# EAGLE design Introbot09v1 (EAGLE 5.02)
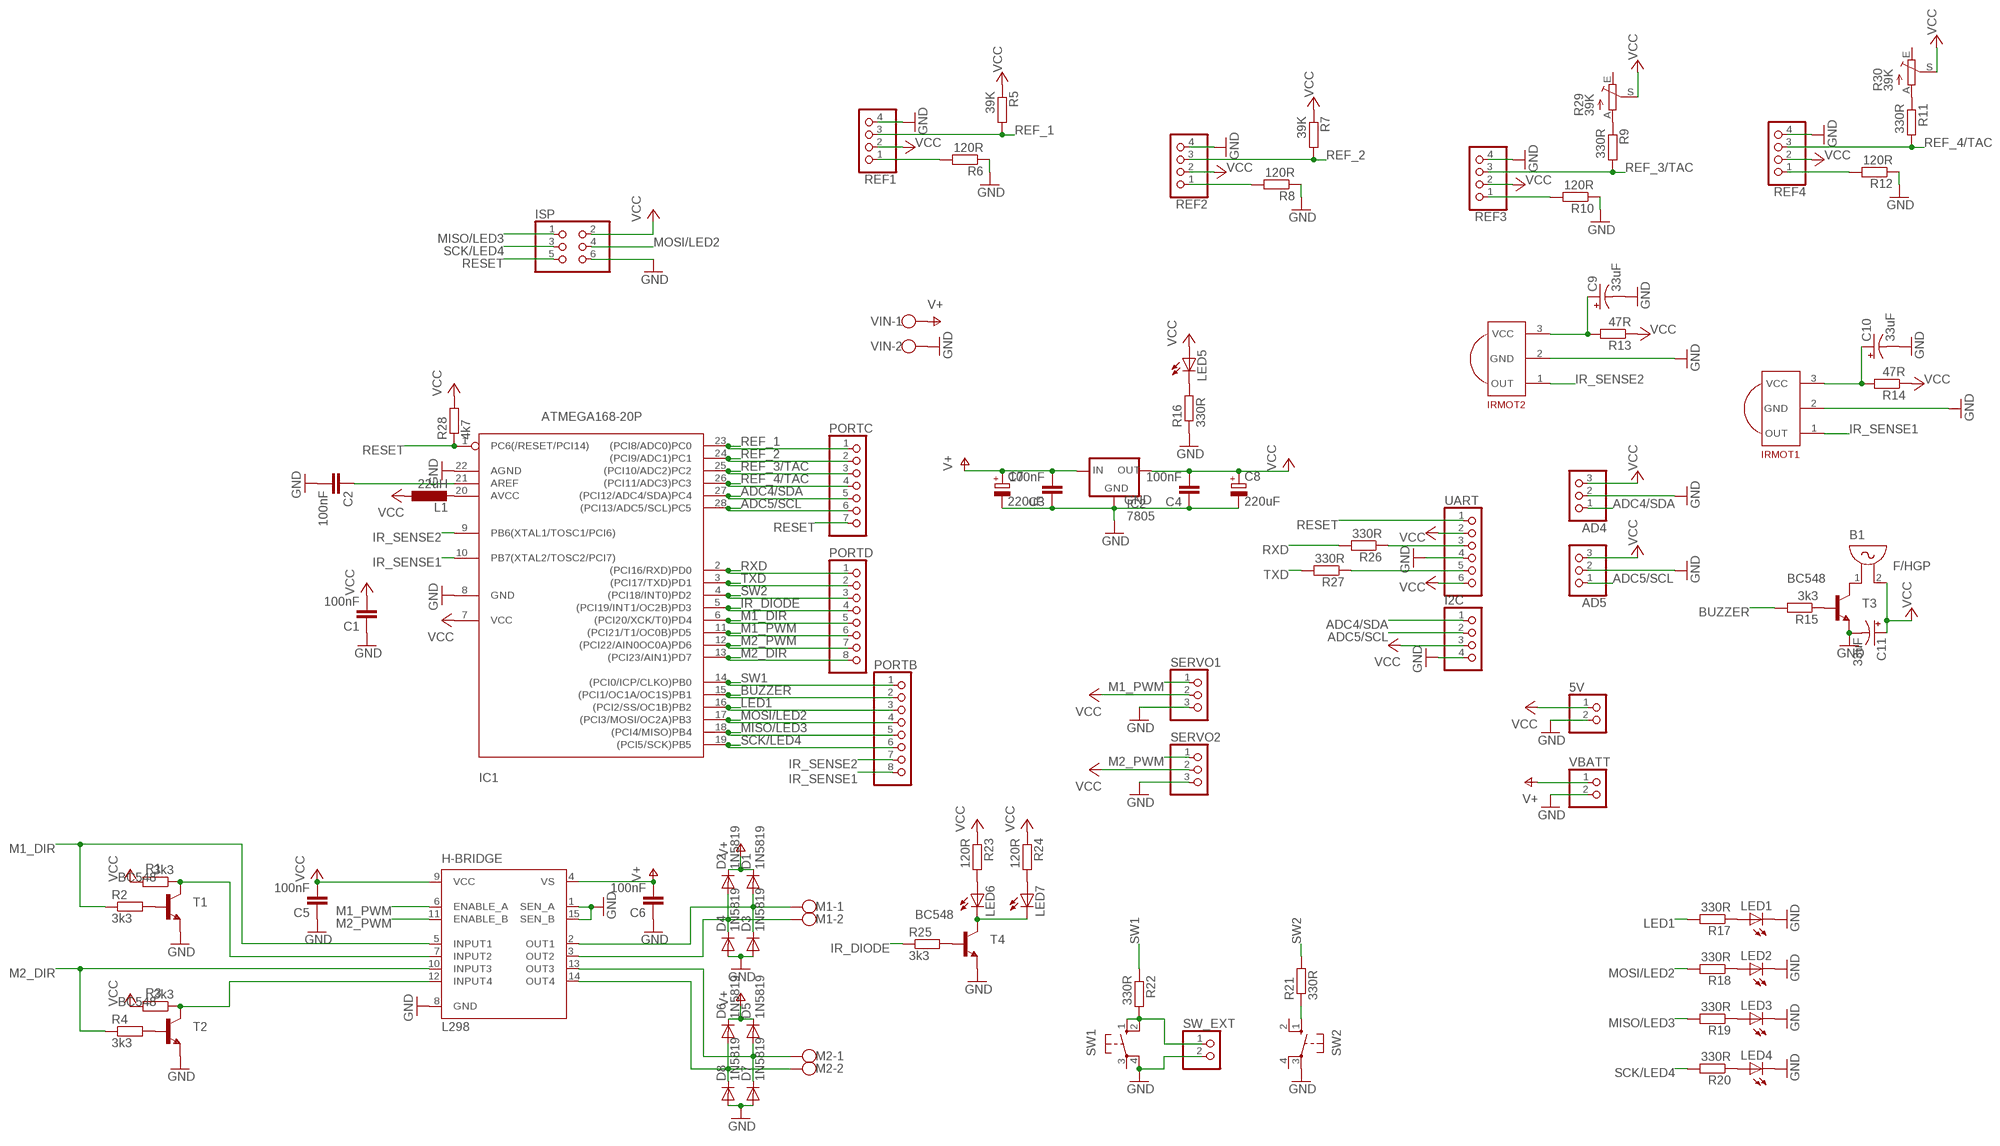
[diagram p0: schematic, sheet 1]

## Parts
5V  PINHD-1X2  [1X02]
AD4  PINHD-1X3H  [1X03]
AD5  PINHD-1X3H  [1X03]
B1  F/HGP  [F/HGP]
C1  100nF  C-EU0207/7  [0207/7]
C2  100nF  C-EU0207/7  [0207/7]
C3  100nF  C-EU0207/7  [0207/7]
C4  100nF  C-EU0207/7  [0207/7]
C5  100nF  C-EU0207/7  [0207/7]
C6  100nF  C-EU0207/7  [0207/7]
C7  220uF  CPOL-EUE5-8.5  [E5-8,5]
C8  220uF  CPOL-EUE5-8.5  [E5-8,5]
C9  33uF  CPOL-USB45181B  [B45181B]
C10  33uF  CPOL-USB45181B  [B45181B]
C11  33uF  CPOL-USB45181B  [B45181B]
D1  1N5819  DIODE-D-7.5  [D-7.5]
D2  1N5819  DIODE-D-7.5  [D-7.5]
D3  1N5819  DIODE-D-7.5  [D-7.5]
D4  1N5819  DIODE-D-7.5  [D-7.5]
D5  1N5819  DIODE-D-7.5  [D-7.5]
D6  1N5819  DIODE-D-7.5  [D-7.5]
D7  1N5819  DIODE-D-7.5  [D-7.5]
D8  1N5819  DIODE-D-7.5  [D-7.5]
H-BRIDGE  L298  [MULTIWATT-15]
I2C  PINHD-1X4OCTAGON  [1X04OCT]
IC1  ATMEGA168-20P  [DIL28-3]
IC2  7805  78XXS  [78XXS]
IRMOT1  IRMOTIRMOT  [IRMOT]
IRMOT2  IRMOTIRMOT  [IRMOT]
ISP  PINHD-2X3  [2X03]
L1  22uH  L-EU0207/7  [0207/7]
LED1  LED3MM  [LED3MM]
LED2  LED3MM  [LED3MM]
LED3  LED3MM  [LED3MM]
LED4  LED3MM  [LED3MM]
LED5  LED3MM  [LED3MM]
LED6  LEDLED5MMH  [LED5MMH]
LED7  LEDLED5MMH  [LED5MMH]
M1  W237-02P  [W237-132]
M2  W237-02P  [W237-132]
PORTB  PINHD-1X8  [1X08]
PORTC  PINHD-1X7  [1X07]
PORTD  PINHD-1X8  [1X08]
R1  3k3  R-EU_0207/7  [0207/7]
R2  3k3  R-EU_0207/7  [0207/7]
R3  3k3  R-EU_0207/7  [0207/7]
R4  3k3  R-EU_0207/7  [0207/7]
R5  39K  R-EU_0207/7  [0207/7]
R6  120R  R-EU_0207/7  [0207/7]
R7  39K  R-EU_0207/7  [0207/7]
R8  120R  R-EU_0207/7  [0207/7]
R9  330R  R-EU_0207/7  [0207/7]
R10  120R  R-EU_0207/7  [0207/7]
R11  330R  R-EU_0207/7  [0207/7]
R12  120R  R-EU_0207/7  [0207/7]
R13  47R  R-EU_0207/7  [0207/7]
R14  47R  R-EU_0207/7  [0207/7]
R15  3k3  R-EU_0207/7  [0207/7]
R16  330R  R-EU_0207/7  [0207/7]
R17  330R  R-EU_0207/7  [0207/7]
R18  330R  R-EU_0207/7  [0207/7]
R19  330R  R-EU_0207/7  [0207/7]
R20  330R  R-EU_0207/7  [0207/7]
R21  330R  R-EU_0207/7  [0207/7]
R22  330R  R-EU_0207/7  [0207/7]
R23  120R  R-EU_0207/7  [0207/7]
R24  120R  R-EU_0207/7  [0207/7]
R25  3k3  R-EU_0207/7  [0207/7]
R26  330R  R-EU_0207/7  [0207/7]
R27  330R  R-EU_0207/7  [0207/7]
R28  4k7  R-EU_0207/7  [0207/7]
R29  39K  TRIM_EU-S63X  [S63X]
R30  39K  TRIM_EU-S63X  [S63X]
REF1  PINHD-1X4OCTAGON  [1X04OCT]
REF2  PINHD-1X4OCTAGON  [1X04OCT]
REF3  PINHD-1X4OCTAGON  [1X04OCT]
REF4  PINHD-1X4OCTAGON  [1X04OCT]
SERVO1  PINHD-1X3H  [1X03]
SERVO2  PINHD-1X3H  [1X03]
SW1  10-XX  [B3F-10XX]
SW2  10-XX  [B3F-10XX]
SW_EXT  PINHD-1X2  [1X02]
T1  BC548  BC548A-NPN-TO92-EBC  [TO92-EBC]
T2  BC548  BC548A-NPN-TO92-EBC  [TO92-EBC]
T3  BC548  BC548A-NPN-TO92-EBC  [TO92-EBC]
T4  BC548  BC548A-NPN-TO92-EBC  [TO92-EBC]
UART  PINHD-1X6  [1X06]
VBATT  PINHD-1X2  [1X02]
VIN  W237-02P  [W237-132]

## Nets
!M1_DIR: H-BRIDGE.7(INPUT2) R1.1 T1.C
!M2_DIR: H-BRIDGE.12(INPUT4) R3.1 T2.C
ADC4/SDA: AD4.1 I2C.1 IC1.27((PCI12/ADC4/SDA)PC4) PORTC.5
ADC5/SCL: AD5.1 I2C.2 IC1.28((PCI13/ADC5/SCL)PC5) PORTC.6
BUZZER: IC1.15((PCI1/OC1A/OC1S)PB1) PORTB.2 R15.2
GND: 5V.2 AD4.2 AD5.2 C1.1 C2.2 C3.1 C4.1 C5.1 C6.1 C7.- C8.- C9.- C10.- C11.- D3.A D4.A D7.A D8.A H-BRIDGE.1(SEN_A) H-BRIDGE.8(GND) H-BRIDGE.15(SEN_B) I2C.4 IC1.8(GND) IC1.22(AGND) IC2.GND IRMOT1.2(GND) IRMOT2.2(GND) ISP.6 LED1.K(C) LED2.K(C) LED3.K(C) LED4.K(C) R6.1 R8.1 R10.1 R12.1 R16.1 REF1.4 REF2.4 REF3.4 REF4.4 SERVO1.3 SERVO2.3 SW1.4(P1) SW2.3(P) SW_EXT.2 T1.E T2.E T3.E T4.E UART.4 VBATT.2 VIN.2
IR_DIODE: IC1.5((PCI19/INT1/OC2B)PD3) PORTD.4 R25.1
IR_SENSE1: IC1.10(PB7(XTAL2/TOSC2/PCI7)) IRMOT1.1(OUT) PORTB.8
IR_SENSE2: IC1.9(PB6(XTAL1/TOSC1/PCI6)) IRMOT2.1(OUT) PORTB.7
LED1: IC1.16((PCI2/SS/OC1B)PB2) PORTB.3 R17.2
M1_DIR: H-BRIDGE.5(INPUT1) IC1.6((PCI20/XCK/T0)PD4) PORTD.5 R2.1
M1_PWM: H-BRIDGE.6(ENABLE_A) IC1.11((PCI21/T1/OC0B)PD5) PORTD.6 SERVO1.1
M2_DIR: H-BRIDGE.10(INPUT3) IC1.13((PCI23/AIN1)PD7) PORTD.8 R4.1
M2_PWM: H-BRIDGE.11(ENABLE_B) IC1.12((PCI22/AIN0OC0A)PD6) PORTD.7 SERVO2.1
MISO/LED3: IC1.18((PCI4/MISO)PB4) ISP.1 PORTB.5 R19.2
MOSI/LED2: IC1.17((PCI3/MOSI/OC2A)PB3) ISP.4 PORTB.4 R18.2
N$1: LED6.P$2(C) LED7.P$2(C) T4.C
N$2: R2.2 T1.B
N$3: LED6.P$1(A) R23.2
N$4: R6.2 REF1.1
N$5: C2.1 IC1.21(AREF)
N$6: R4.2 T2.B
N$7: IC1.20(AVCC) L1.2
N$8: R8.2 REF2.1
N$9: R10.2 REF3.1
N$10: R9.1 R29.A
N$11: R12.2 REF4.1
N$12: R11.1 R30.A
N$13: C9.+ IRMOT2.3(VCC) R13.2
N$14: C10.+ IRMOT1.3(VCC) R14.2
N$15: R26.1 UART.3
N$16: R27.1 UART.5
N$17: B1.1 T3.C
N$18: R15.1 T3.B
N$19: LED5.K(C) R16.2
N$20: LED1.A R17.1
N$21: LED2.A R18.1
N$22: LED3.A R19.1
N$23: LED4.A R20.1
N$24: R21.1 SW2.1(S)
N$25: R22.2 SW1.1(S) SW1.2(S1) SW_EXT.1
N$26: R25.2 T4.B
N$27: LED7.P$1(A) R24.2
N$29: D1.A D3.C H-BRIDGE.2(OUT1) M1.1
N$30: D2.A D4.C H-BRIDGE.3(OUT2) M1.2
N$31: D5.A D7.C H-BRIDGE.13(OUT3) M2.1
N$32: D6.A D8.C H-BRIDGE.14(OUT4) M2.2
REF_1: IC1.23((PCI8/ADC0)PC0) PORTC.1 R5.2 REF1.3
REF_2: IC1.24((PCI9/ADC1)PC1) PORTC.2 R7.2 REF2.3
REF_3/TAC: IC1.25((PCI10/ADC2)PC2) PORTC.3 R9.2 REF3.3
REF_4/TAC: IC1.26((PCI11/ADC3)PC3) PORTC.4 R11.2 REF4.3
RESET: IC1.1(PC6(/RESET/PCI14)) ISP.5 PORTC.7 R28.1 UART.1
RXD: IC1.2((PCI16/RXD)PD0) PORTD.1 R26.2
SCK/LED4: IC1.19((PCI5/SCK)PB5) ISP.3 PORTB.6 R20.2
SW1: IC1.14((PCI0/ICP/CLKO)PB0) PORTB.1 R22.1
SW2: IC1.4((PCI18/INT0)PD2) PORTD.3 R21.2
TXD: IC1.3((PCI17/TXD)PD1) PORTD.2 R27.2
V+: C3.2 C6.2 C7.+ D1.C D2.C D5.C D6.C H-BRIDGE.4(VS) IC2.IN VBATT.1 VIN.1
VCC: 5V.1 AD4.3 AD5.3 B1.2 C1.2 C4.2 C5.2 C8.+ C11.+ H-BRIDGE.9(VCC) I2C.3 IC1.7(VCC) IC2.OUT ISP.2 L1.1 LED5.A R1.2 R3.2 R5.1 R7.1 R13.1 R14.1 R23.1 R24.1 R28.2 R29.S R30.S REF1.2 REF2.2 REF3.2 REF4.2 SERVO1.2 SERVO2.2 UART.2 UART.6
Unconnected: R29.E R30.E SW1.3(P) SW2.2(S1) SW2.4(P1)

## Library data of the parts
5V SW_EXT VBATT = pinhead:PINHD-1X2: PIN HEADER
AD4 AD5 SERVO1 SERVO2 = pinhead:PINHD-1X3: PIN HEADER
B1 = buzzer:F/HGP: BUZZER
C1-C6 = rcl:C-EU: CAPACITOR, European symbol
C7 C8 = rcl:CPOL-EU: POLARIZED CAPACITOR, European symbol
C9-C11 = rcl:CPOL-US: POLARIZED CAPACITOR, American symbol
D1-D8 = diode:DIODE-: DIODE
H-BRIDGE = st-microelectronics:L298: DUAL FULL-BRIDGE DRIVER
I2C REF1-REF4 = pinhead:PINHD-1X4: PIN HEADER
IC1 = avr:ATMEGA168*P: MICROCONTROLLER 16 kBytes FLASH 1 kBytes SRAM 512 Bytes EEPROM USART 8-channel 10 bit ADC
IC2 = v-reg:78XXS: VOLTAGE REGULATOR
IRMOT1 IRMOT2 = Victor:IRMOT
ISP = pinhead:PINHD-2X3: PIN HEADER
L1 = rcl:L-EU: INDUCTOR, European symbol
LED1-LED7 = led:LED: LED
M1 M2 VIN = con-wago-508:W237-02P: WAGO SREW CLAMP
PORTB PORTD = pinhead:PINHD-1X8: PIN HEADER
PORTC = pinhead:PINHD-1X7: PIN HEADER
R1-R28 = rcl:R-EU_: RESISTOR, European symbol
R29 R30 = pot:TRIM_EU-: POTENTIOMETER
SW1 SW2 = switch-omron:10-XX: OMRON SWITCH
T1-T4 = transistor:*-NPN-: NPN Transistror
UART = pinhead:PINHD-1X6: PIN HEADER

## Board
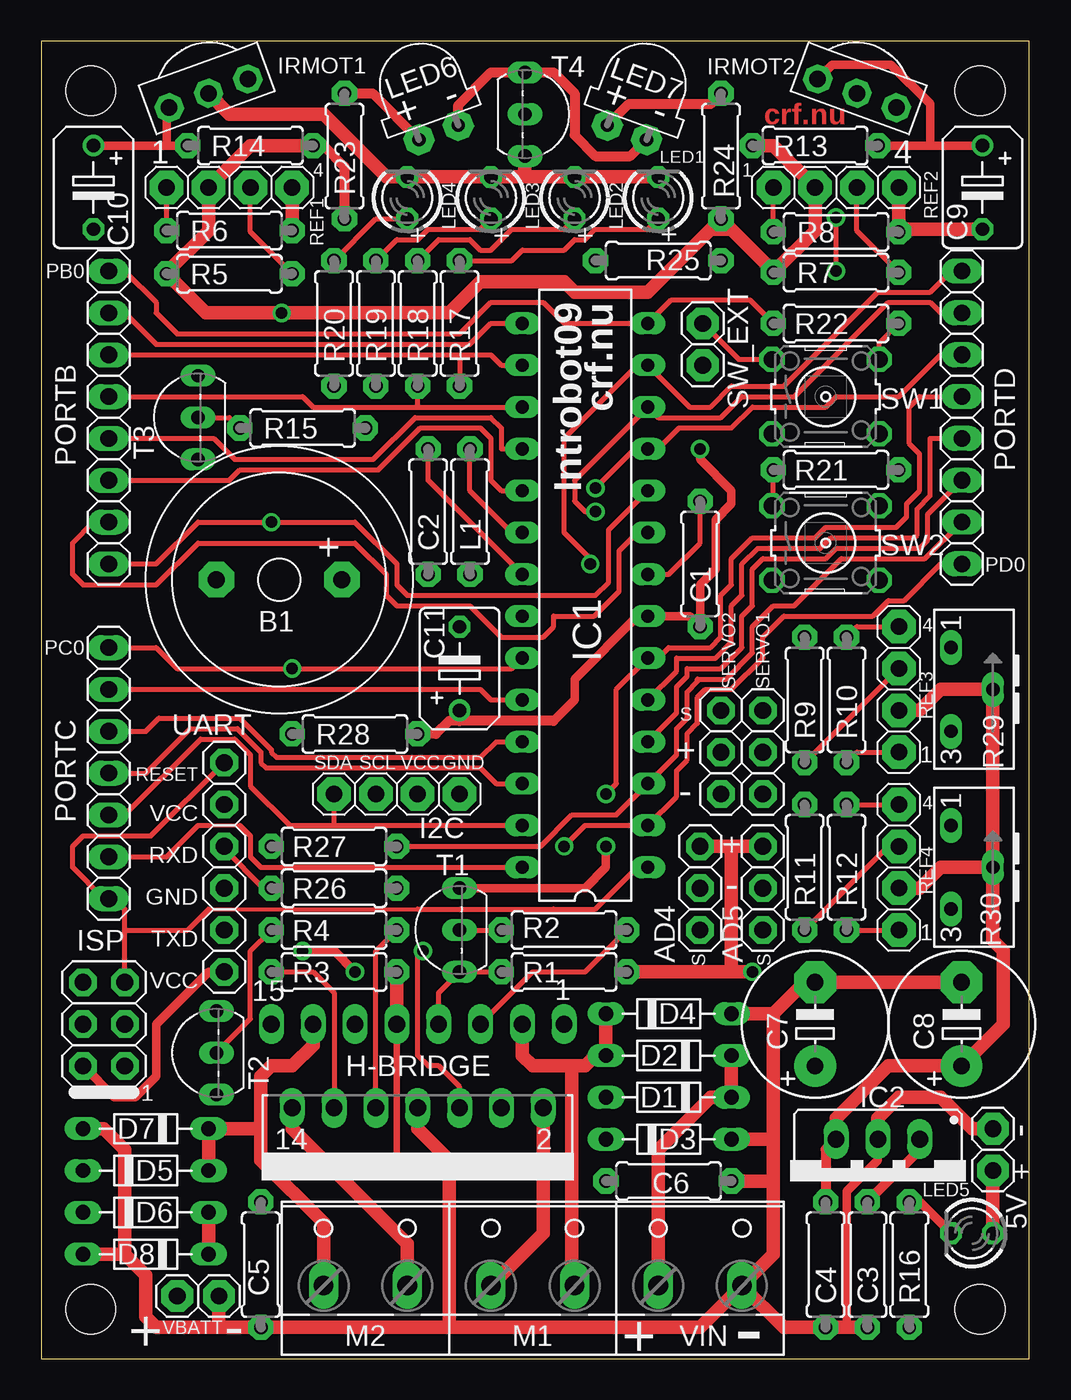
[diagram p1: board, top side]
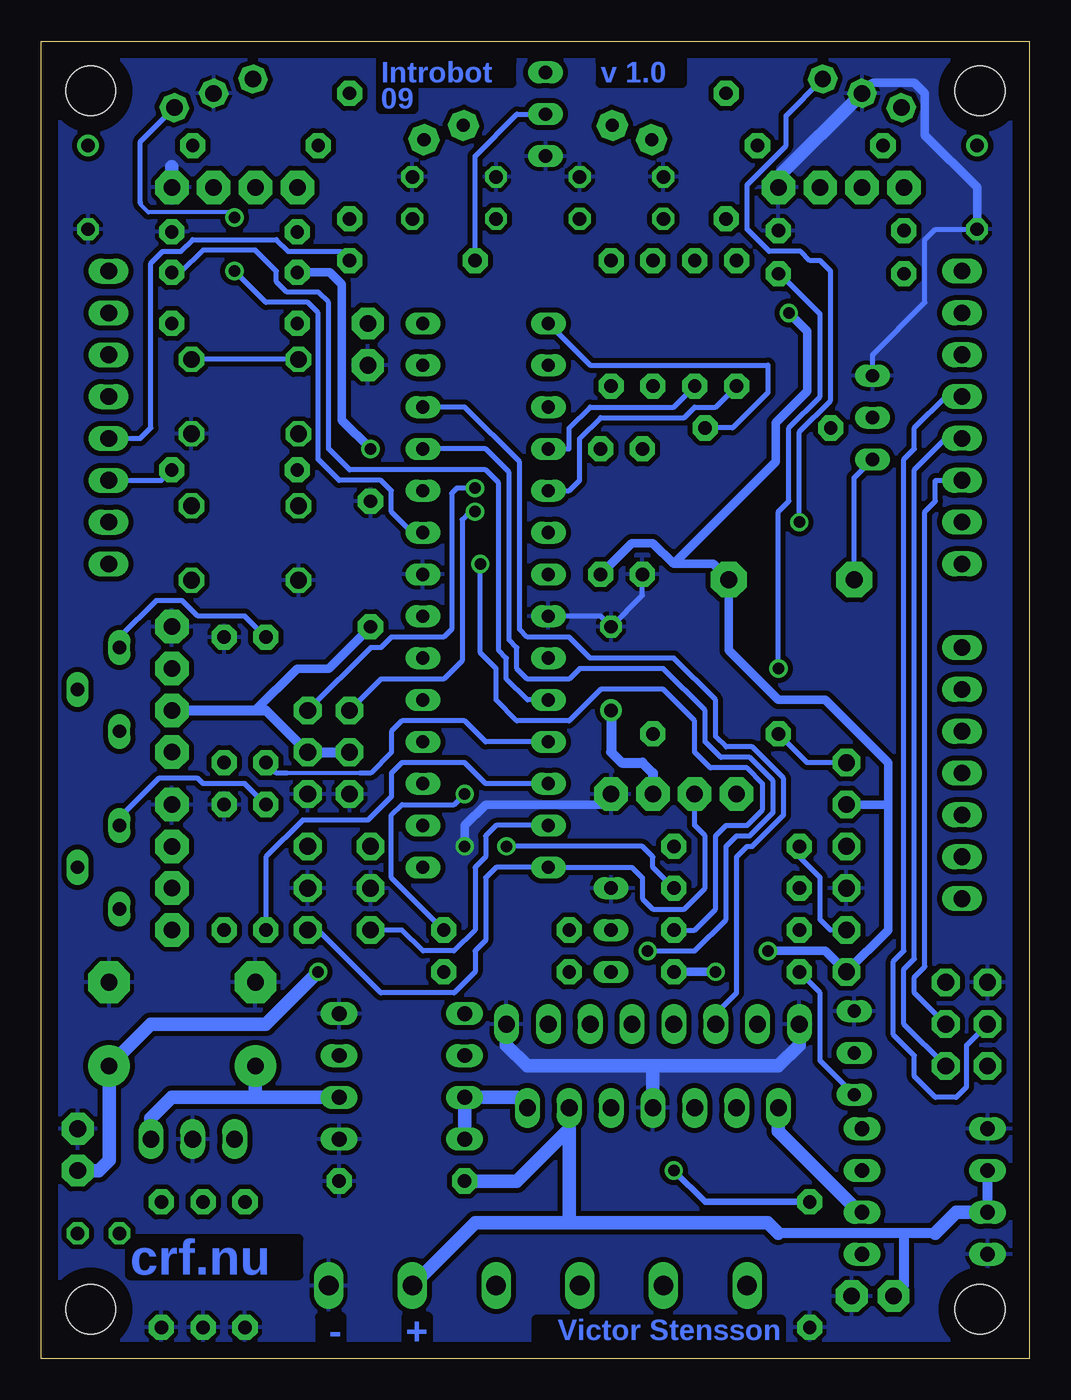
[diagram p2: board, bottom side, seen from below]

Size 60 x 80 mm. Coordinates in mm from the lower left corner, seen from the top.
Outline: 0,0 60,0 60,80 0,80 0,0
Copper layers (1*16): Top 0.035mm / dielectric 1.5mm / Bottom 0.035mm
Design rules "10mils *": minimum track width 10mil, minimum drill 0.7mm, track to track 10mil, track to pad 10mil, pad to pad 20mil, via to via 10mil, smd to smd 10mil, copper to edge 40mil, drill to drill 10mil, minimum pad ring 10mil, minimum via ring 8mil, stop-mask expansion 0mil, vias tented up to drill 0mil, thermal gap 10mil
Holes 3 mm at 57,3 57,77 3,77 3,3

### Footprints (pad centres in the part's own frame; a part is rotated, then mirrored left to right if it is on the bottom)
1X02 = drill 1.016 pad 1.93 octagon: 1 -1.27,0; 2 1.27,0
1X03 = drill 1.016 pad 1.676 octagon: 1 -2.54,0; 2 0,0; 3 2.54,0
F/HGP = drill 1.016 pad 2.159 octagon: 1 -3.81,0; 2 3.81,0
0207/7 = drill 0.813 pad 1.524 octagon: 1 -3.81,0; 2 3.81,0
E5-8,5 = drill 1.016 pad 2.54 round: + -2.54,0 | drill 1.016 pad 2.54 octagon: - 2.54,0
B45181B = drill 0.813 round: + -2.54,0 | drill 0.813 octagon: - 2.54,0
D-7.5 = drill 0.9 long: A 3.81,0; C -3.81,0
MULTIWATT-15 = drill 1.016 long: 1 -8.89,-7.62; 2 -7.62,-2.54; 3 -6.35,-7.62; 4 -5.08,-2.54; 5 -3.81,-7.62; 6 -2.54,-2.54; 7 -1.27,-7.62; 8 0,-2.54; 9 1.27,-7.62; 10 2.54,-2.54; 11 3.81,-7.62; 12 5.08,-2.54; 13 6.35,-7.62; 14 7.62,-2.54; 15 8.89,-7.62
1X04OCT = drill 1 pad 2.032 octagon: 1 -3.81,0; 2 -1.27,0; 3 1.27,0; 4 3.81,0
DIL28-3 = drill 0.813 long: 1 -16.51,-3.81; 2 -13.97,-3.81; 3 -11.43,-3.81; 4 -8.89,-3.81; 5 -6.35,-3.81; 6 -3.81,-3.81; 7 -1.27,-3.81; 8 1.27,-3.81; 9 3.81,-3.81; 10 6.35,-3.81; 11 8.89,-3.81; 12 11.43,-3.81; 13 13.97,-3.81; 14 16.51,-3.81; 15 16.51,3.81; 16 13.97,3.81; 17 11.43,3.81; 18 8.89,3.81; 19 6.35,3.81; 20 3.81,3.81; 21 1.27,3.81; 22 -1.27,3.81; 23 -3.81,3.81; 24 -6.35,3.81; 25 -8.89,3.81; 26 -11.43,3.81; 27 -13.97,3.81; 28 -16.51,3.81
78XXS = drill 1.016 long: GND 0,-2.54; IN -2.54,-2.54; OUT 2.54,-2.54
IRMOT = drill 1 pad 1.676 octagon: 1 2.54,0; 2 0,0; 3 -2.54,0
2X03 = drill 1.016 pad 1.676 octagon: 1 -2.54,-1.27; 2 -2.54,1.27; 3 0,-1.27; 4 0,1.27; 5 2.54,-1.27; 6 2.54,1.27
LED3MM = drill 0.813 octagon: A -1.27,0; K 1.27,0
LED5MMH = drill 0.8 pad 1.778 octagon: P$1 -1.27,0; P$2 1.27,0
W237-132 = drill 1.194 long: 1 -2.54,-0.635; 2 2.54,-0.635
1X08 = drill 1.016 long: 1 -8.89,0; 2 -6.35,0; 3 -3.81,0; 4 -1.27,0; 5 1.27,0; 6 3.81,0; 7 6.35,0; 8 8.89,0
1X07 = drill 1.016 long: 1 -7.62,0; 2 -5.08,0; 3 -2.54,0; 4 0,0; 5 2.54,0; 6 5.08,0; 7 7.62,0
S63X = drill 0.813 long: A 2.54,0; E -2.54,0; S 0,-2.54
B3F-10XX = drill 1.016 octagon: 1 -3.251,2.261; 2 3.251,2.261; 3 -3.251,-2.261; 4 3.251,-2.261
TO92-EBC = drill 0.813 long: B 0,-1.27; C -2.54,-1.27; E 2.54,-1.27
1X06 = drill 1.016 pad 1.676 octagon: 1 -6.35,0; 2 -3.81,0; 3 -1.27,0; 4 1.27,0; 5 3.81,0; 6 6.35,0

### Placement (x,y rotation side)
5V  57.78,12.7 90 top
AD4  40.01,28.57 90 top
AD5  43.81,28.57 90 top
B1  14.45,47.31 0 top
C1  40.01,48.26 270 top
C2  23.5,51.44 270 top
C3  50.16,5.71 90 top
C4  47.62,5.71 90 top
C5  13.34,5.71 90 top
C6  38.1,10.79 180 top
C7  46.99,20.32 90 top
C8  55.88,20.32 90 top
C9  57.15,71.12 270 top
C10  3.17,71.12 270 top
C11  25.4,41.91 90 top
D1  38.1,15.88 180 top
D2  38.1,18.41 180 top
D3  38.1,13.34 0 top
D4  38.1,20.95 0 top
D5  6.35,11.43 0 top
D6  6.35,8.89 0 top
D7  6.35,13.97 180 top
D8  6.35,6.35 180 top
H-BRIDGE  22.86,12.7 180 top
I2C  21.59,34.29 0 top
IC1  33.02,46.35 90 top
IC2  50.8,10.79 180 top
IRMOT1  10.16,76.83 20 top
IRMOT2  49.53,76.83 340 top
ISP  3.81,20.32 90 top
L1  26.04,51.44 90 top
LED1  37.47,70.48 90 top
LED2  32.38,70.48 90 top
LED3  27.3,70.48 90 top
LED4  22.23,70.48 90 top
LED5  56.52,7.62 180 top
LED6  24.13,74.45 20 top
LED7  35.56,74.45 340 top
M1  29.84,5.08 0 top
M2  19.68,5.08 0 top
PORTB  4.1,57.15 270 top
PORTC  4.1,35.56 270 top
PORTD  55.9,57.15 90 top
R1  31.75,23.5 0 top
R2  31.75,26.04 180 top
R3  17.78,23.5 0 top
R4  17.78,26.04 180 top
R5  11.43,65.88 0 top
R6  11.43,68.5 180 top
R7  48.26,65.96 0 top
R8  48.26,68.42 180 top
R9  46.35,40.01 270 top
R10  48.9,40.01 270 top
R11  46.35,29.84 270 top
R12  48.9,29.84 270 top
R13  46.99,73.66 0 top
R14  12.7,73.66 180 top
R15  15.88,56.52 0 top
R16  52.7,5.71 90 top
R17  25.4,62.87 270 top
R18  22.86,62.87 270 top
R19  20.32,62.87 270 top
R20  17.78,62.87 270 top
R21  48.26,53.98 0 top
R22  48.26,62.87 0 top
R23  18.41,73.03 90 top
R24  41.27,73.03 90 top
R25  37.47,66.67 180 top
R26  17.78,28.57 0 top
R27  17.78,31.11 0 top
R28  19.05,37.94 0 top
R29  55.24,40.64 90 top
R30  55.24,29.84 90 top
REF1  11.43,71.12 0 top
REF2  48.26,71.12 0 top
REF3  52.07,40.64 90 top
REF4  52.07,29.84 90 top
SERVO1  43.81,36.83 270 top
SERVO2  41.27,36.83 270 top
SW1  47.62,58.42 0 top
SW2  47.62,49.53 0 top
SW_EXT  40.16,61.59 270 top
T1  24.13,26.04 90 top
T2  9.37,18.57 90 top
T3  8.26,57.15 90 top
T4  30.64,75.56 270 top
UART  11.11,29.84 270 top
VBATT  9.53,3.81 0 top
VIN  40.01,5.08 0 top

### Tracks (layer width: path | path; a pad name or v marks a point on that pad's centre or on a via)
!M1_DIR
  Top 0.305: H-BRIDGE.7 24.13,22.23 T1.C R1.1
!M2_DIR
  Top 0.305: H-BRIDGE.12 17.78,22.23 16.51,23.5 R3.1
  Bottom 0.305: R3.1 12.7,22.23 12.7,18.1 T2.C
ADC4/SDA
  Top 0.305: 17.78,32.38 I2C.1 | 17.78,32.38 IC1.27 | PORTC.5 5.08,33.02 9.68,37.62 11.75,37.62 12.7,36.67 12.7,34.77 15.08,32.38 17.78,32.38
  Bottom 0.305: AD4.1 38.1,26.04 36.83,24.77 34.92,24.77 33.66,26.04 33.66,29.84 33.02,30.48 33.02,31.75 32.38,32.38 IC1.27
ADC5/SCL
  Top 0.254: 10.16,32.38 12.06,32.38
  Top 0.305: IC1.28 13.34,29.84 12.7,30.48 12.7,31.75 12.06,32.38 | PORTC.6 7.62,30.48 9.53,32.38 10.16,32.38
  Bottom 0.305: I2C.2 20.32,32.38 19.68,31.75 19.68,28.57 20.95,27.3 22.86,27.3 23.5,27.94 23.5,29.21 24.13,29.84 IC1.28 32.38,29.84 33.02,29.21 33.02,25.4 33.66,24.77 33.66,23.5 34.92,22.23 39.37,22.23 43.18,26.04 AD5.1
BUZZER
  Top 0.305: IC1.15 27.3,62.87 26.04,61.59 6.99,61.59 5.08,63.5 PORTB.2
  Bottom 0.305: IC1.15 26.67,60.33 15.88,60.33 15.88,58.66 18.02,56.52 R15.2
GND  (via drill 0.7)
  Top 0.305: REF3.4 49.53,44.45 R10.1 | R12.1 REF4.4 | IC1.8 38.1,47.62 40.01,49.53 C1.1
  Top 0.508: IC2.GND 50.8,12.06 48.9,10.16 48.9,1.91 | T1.E 33.02,28.57 34.29,29.84 v34.29,31.11
  Top 0.813: VIN.2 40.01,1.91 24.77,1.91 | 24.77,1.91 24.77,12.06 22.86,13.97 H-BRIDGE.8 | 10.79,1.91 VBATT.2 | 24.77,1.91 C5.1 10.79,1.91 | D7.A 3.81,13.97 5.08,12.7 5.08,6.35 | 5.08,6.35 D8.A | 44.45,20.95 D4.A | VIN.2 45.09,1.91 C3.1 | C3.1 48.9,1.91 C4.1 C3.1 | C8.- C7.- 46.35,22.86 44.45,20.95 | IC2.GND 50.8,14.61 52.07,15.88 54.61,15.88 56.52,13.97 5V.2 | R8.1 REF2.4 | R8.1 | C9.- 52.23,68.58 R8.1 | 5.08,6.35 6.35,5.08 6.35,2.54 6.99,1.91 10.79,1.91 | REF1.4 R6.1 | 44.45,10.79 44.45,6.35 VIN.2 | 44.45,10.79 44.45,13.34 | 44.45,13.34 44.45,20.95 | 44.45,10.79 C6.1 | 44.45,13.34 D3.A | IRMOT1.2 11.43,75.56 17.14,75.56 20.95,71.75 LED4.K LED3.K 29.37,71.75 | 29.37,71.75 LED2.K LED1.K | 29.37,71.75 T4.E
  Bottom 0.305: C2.2 23.5,46.35 C11.- 26.04,45.09 IC1.22 | T3.E 9.53,60.96 6.35,64.14 6.35,67.94 5.71,68.58 C10.-
  Bottom 0.508: C10.- 3.17,71.12 6.35,74.3 6.35,76.83 6.99,77.47 9.53,77.47 IRMOT1.2 | v34.29,31.11 34.29,32.38 33.02,33.66 26.04,33.66 I2C.4
  Bottom 0.813: H-BRIDGE.15 13.97,19.05 15.24,17.78 22.86,17.78 | 22.86,17.78 30.48,17.78 31.75,19.05 H-BRIDGE.1 | H-BRIDGE.8 22.86,17.78 | REF1.4 15.24,71.75 IRMOT1.2 | REF2.4 52.07,72.39
  pour Bottom (isolate 0.305): 0,80.01 0,0 60.33,0 60.33,80.01
IR_DIODE
  Top 0.305: PORTD.4 53.98,55.88 53.98,52.39 53.18,51.59 53.18,50.01 53.02,49.85 47.94,49.85 47.31,49.21 43.5,49.21 42.55,48.26 42.55,46.35 41.91,45.72 41.91,43.5 40.96,42.55 38.58,42.55 38.58,41.75 IC1.5
  Bottom 0.305: 53.34,56.52 53.98,55.88 PORTD.4 | 53.34,56.52 | 53.34,56.52 53.34,66.52 52.63,67.23 51.51,67.23 50.8,67.94 45.72,67.94 45.01,67.23 41.83,67.23 R25.1 | 53.34,56.52
IR_SENSE1  (via drill 0.7)
  Top 0.305: IC1.10 34.45,50.32 34.45,47.15 33.66,46.35 22.23,46.35 21.59,46.99 21.59,48.26 19.05,50.8 v13.97,50.8 9.53,50.8 6.99,48.26 PORTB.8
  Bottom 0.305: v13.97,50.8 13.97,56.28 12.06,58.18 12.06,66.04 12.7,66.67 13.34,66.67 13.89,67.23 15.8,67.23 17.14,68.58 17.14,71.28 14.76,73.66 14.76,75.49 IRMOT1.1
IR_SENSE2  (via drill 0.7)
  Top 0.305: IC1.9 36.2,50.16 35.08,49.05 35.08,46.59 33.58,45.09 31.11,45.09 31.11,44.45 30.48,43.81 27.94,43.81 26.04,45.72 21.59,45.72 20.95,46.35 20.95,47.62 19.05,49.53 9.53,49.53 6.99,46.99 2.54,46.99 1.91,47.62 1.91,49.53 3.17,50.8 PORTB.7 | v48.26,66.04 v48.26,69.29
  Bottom 0.254: v48.26,69.29 48.58,69.61 53.5,69.61 53.98,70.09 53.98,70.17
  Bottom 0.305: v48.26,66.04 46.35,64.14 43.81,64.14 43.18,63.5 43.18,54.61 41.91,53.34 39.37,53.34 38.73,52.7 38.73,51.44 37.47,50.16 IC1.9 | IRMOT2.1 53.98,73.91 53.98,70.17
LED1
  Top 0.305: IC1.16 27.94,60.33 27.3,60.96 25.4,60.96 | PORTB.3 25.4,60.96 | 25.4,60.96 R17.2
M1_DIR  (via drill 0.7)
  Top 0.305: v34.29,34.29 34.92,34.92 34.92,40.64 IC1.6 37.47,42.55 38.1,43.18 40.64,43.18 41.27,43.81 41.27,46.35 41.91,46.99 41.91,48.58 43.18,49.85 46.99,49.85 47.62,50.48 51.91,50.48 52.55,51.12 52.55,51.91 53.34,52.7 53.34,54.93 52.7,55.56 52.7,57.78 53.34,58.42 PORTD.5 | R2.1 33.02,23.5 29.84,23.5 H-BRIDGE.5
  Bottom 0.305: R2.1 38.73,29.21 38.73,33.02 38.1,33.66 34.92,33.66 v34.29,34.29
M1_PWM  (via drill 0.7)
  Top 0.305: H-BRIDGE.6 25.4,16.51 24.13,17.78 23.5,17.78 22.86,18.41 22.86,24.45 v23.18,24.77 | PORTD.6 54.61,60.96 52.07,58.42 48.26,58.42 47.62,57.78 43.18,57.78 41.91,56.52 38.73,56.52 37.47,55.24 IC1.11 36.04,55.24 v33.66,52.86
  Bottom 0.305: v23.18,24.77 20.32,24.77 18.41,26.67 18.41,31.11 17.78,31.75 16.99,31.75 15.56,33.18 15.56,35.08 16.99,36.51 18.73,36.51 19.68,37.47 19.68,39.37 22.23,41.91 27.3,41.91 27.94,41.27 30.48,41.27 31.11,41.91 31.11,43.18 31.59,43.66 31.59,53.82 33.02,55.24 IC1.11 | SERVO1.1 40.01,43.18 39.37,43.18 38.73,43.81 35.56,43.81 35.08,44.29 35.08,52.55 34.77,52.86 v33.66,52.86
M2_DIR  (via drill 0.7)
  Top 0.305: H-BRIDGE.10 20.32,24.77 R4.1 | PORTD.8 55.24,66.04 53.98,64.77 50.8,64.77 45.09,59.05 41.91,59.05 40.64,57.78 39.37,57.78 IC1.13 36.2,60.33 31.75,55.88 31.75,50.16 33.34,48.58 v33.34,48.26
  Bottom 0.305: R4.1 20.32,26.04 19.05,27.3 19.05,31.75 18.41,32.38 17.14,32.38 16.19,33.34 16.19,34.92 17.14,35.88 19.37,35.88 20.32,36.83 20.32,38.73 22.23,40.64 26.04,40.64 27.94,38.73 31.11,38.73 32.38,40.01 32.38,41.91 33.34,42.86 v33.34,48.26
M2_PWM  (via drill 0.7)
  Top 0.305: PORTD.7 54.61,63.5 53.98,64.14 51.44,64.14 45.72,58.42 42.55,58.42 41.27,57.15 37.47,57.15 IC1.12 32.38,53.34 32.38,52.07 33.02,51.44 v33.66,51.44
  Bottom 0.305: H-BRIDGE.11 19.05,20.95 17.78,22.23 17.78,30.48 17.14,31.11 16.83,31.11 14.92,33.02 14.92,35.24 16.83,37.15 18.41,37.15 19.05,37.78 19.05,40.01 21.59,42.55 26.67,42.55 27.94,43.81 30.48,43.81 30.96,44.29 30.96,54.45 34.29,57.78 IC1.12 | SERVO2.1 39.37,41.27 35.56,41.27 34.45,42.39 34.45,50.96 33.97,51.44 v33.66,51.44
MISO/LED3
  Top 0.305: IC1.18 27.94,55.24 27.94,56.52 27.3,57.15 22.7,57.15 20.16,54.61 11.75,54.61 10.48,55.88 PORTB.5
  Bottom 0.305: R19.2 21.59,57.78 26.67,57.78 27.94,56.52 27.94,55.24 IC1.18 | PORTB.5 5.08,55.88 6.99,53.98 6.99,24.29 7.62,23.65 7.62,20.32 ISP.1
MOSI/LED2
  Top 0.305: 22.86,57.78 16.51,57.78 15.88,58.42 PORTB.4 | 22.86,57.78 IC1.17 | 22.86,57.78 R18.2
  Bottom 0.305: ISP.4 3.81,19.05 3.81,16.51 4.45,15.88 5.71,15.88 6.99,17.14 6.99,18.41 8.26,19.68 8.26,24.13 7.62,24.77 7.62,54.61 6.99,55.24 6.99,56.52 5.08,58.42 PORTB.4
N$1
  Top 0.61: LED7.P$2 35.76,73.03 33.66,73.03 32.38,74.3 32.38,76.83 31.11,78.11 T4.C 27.3,78.11 25.32,76.12 LED6.P$2
N$2
  Top 0.305: T1.B R2.2
N$3
  Top 0.61: LED6.P$1 20.12,76.83 R23.2
N$4
  Top 0.305: R6.2 REF1.1
N$5
  Top 0.305: C2.1 23.5,53.34 IC1.21
N$6
  Top 0.305: R4.2 12.7,24.77 12.7,20.64 T2.B
N$7
  Top 0.305: L1.2 26.04,52.7 28.57,50.16 IC1.20
N$8
  Top 0.305: R8.2 REF2.1
N$9
  Top 0.305: REF3.1 49.53,36.83 R10.2
N$10
  Bottom 0.305: R29.A 55.24,43.81 53.02,46.04 51.44,46.04 50.48,45.09 47.62,45.09 R9.1
N$11
  Top 0.305: R12.2 REF4.1
N$12
  Bottom 0.305: R30.A 55.24,32.86 52.86,35.24 50.48,35.24 50.16,34.92 47.62,34.92 R11.1
N$13
  Top 0.508: 53.98,73.66 53.98,76.2 51.59,78.58 48.02,78.58 IRMOT2.3 | 53.98,73.66 C9.+ | 53.98,73.66 R13.2
N$14
  Top 0.508: C10.+ 7.62,73.66 | 7.62,73.66 R14.2 | IRMOT1.3 7.62,75.81 7.62,73.66
N$15
  Top 0.305: R26.1 13.49,28.57 11.11,30.96 UART.3
N$16
  Bottom 0.305: R27.1 13.97,30.48 12.7,29.21 12.7,26.67 12.06,26.04 UART.5
N$17
  Bottom 0.305: B1.1 10.64,53.5 T3.C
N$18
  Top 0.305: R15.1 11.43,57.15 T3.B
N$19
  Top 0.508: LED5.K 53.34,9.53 R16.2
N$20
  Top 0.305: R17.1 28.57,66.67 29.21,67.31 31.75,67.31 32.38,67.94 33.02,67.94 33.66,68.58 36.83,68.58 LED1.A
N$21
  Top 0.305: R18.1 24.13,67.94 26.04,67.94 26.67,67.31 27.3,67.31 28.57,68.58 31.75,68.58 LED2.A
N$22
  Top 0.305: R19.1 21.59,67.94 22.86,67.94 23.5,68.58 26.67,68.58 LED3.A
N$23
  Top 0.305: R20.1 20.32,69.22 LED4.A
N$24
  Top 0.305: SW2.1 44.45,51.87 R21.1
N$25
  Top 0.305: SW1.2 50.88,61.67 R22.2 | SW1.1 42.35,60.68 SW_EXT.1
  Bottom 0.305: SW1.1 50.2,60.68 50.24,60.72 50.88,60.72 | 50.88,60.72 SW1.2 | 50.88,60.72 50.96,60.8
N$26
  Bottom 0.305: R25.2 33.66,73.03 31.11,75.56 T4.B
N$27
  Top 0.61: R24.2 40.64,76.2 35.68,76.2 LED7.P$1
N$29
  Top 0.813: M1.1 30.48,7.62 H-BRIDGE.2
  Bottom 0.813: D3.C D1.A 31.11,15.88 H-BRIDGE.2
N$30
  Top 0.813: H-BRIDGE.3 29.21,18.41 29.84,17.78 32.23,17.78 | M1.2 32.23,4.6 32.23,17.78 | 32.23,17.78 33.02,17.78 33.66,18.41 D2.A D4.C
N$31
  Top 0.813: H-BRIDGE.13 16.51,19.05 15.24,17.78 13.97,17.78 13.34,17.14 13.34,13.97 | D5.A D7.C 13.34,13.97 | M2.1 17.14,8.26 13.34,12.06 13.34,13.97
N$32
  Top 0.813: D8.C D6.A | H-BRIDGE.14 15.24,13.97 22.23,6.99 M2.2
  Bottom 0.813: D6.A 10.32,8.89 15.24,13.81 H-BRIDGE.14
REF_1  (via drill 0.7)
  Top 0.305: PORTC.1 6.99,43.18 8.26,41.91 v15.24,41.91 28.57,41.91 IC1.23 | REF1.3 12.7,68.42 R5.2
  Bottom 0.305: v15.24,41.91 15.24,51.44 14.61,52.07 14.61,56.52 12.7,58.42 12.7,63.42 | 12.7,63.42 | R5.2 15.16,65.88 12.7,63.42
REF_2
  Top 0.305: IC1.24 27.3,40.01 26.67,40.64 PORTC.2 | REF2.3 49.53,68.5 R7.2
  Bottom 0.305: IC1.24 30.48,40.01 31.75,41.27 31.75,42.55 32.23,43.02 32.23,53.18 33.02,53.98 41.27,53.98 42.55,55.24 42.55,64.14 43.18,64.77 45.09,64.77 45.72,65.41 45.72,66.04 46.99,67.31 50.16,67.31 51.51,65.96 R7.2
REF_3/TAC
  Top 0.305: R9.2 REF3.3 | PORTC.3 6.35,38.1 7.14,38.89 12.06,38.89 13.97,36.99 13.97,36.83 14.29,36.51 26.67,36.51 27.62,37.47 IC1.25
  Bottom 0.254: 40.64,35.56 45.09,35.56
  Bottom 0.305: IC1.25 33.02,37.47 34.29,38.73 38.1,38.73 38.73,38.1 38.73,36.83 40.01,35.56 40.64,35.56 | R9.2 45.72,35.56 45.09,35.56
REF_4/TAC
  Top 0.305: REF4.3 51.44,31.11 R11.2 | PORTC.4 6.35,35.56 9.05,38.26 11.91,38.26 13.34,36.83 13.34,36.2 13.65,35.88 26.67,35.88 27.62,34.92 IC1.26
  Bottom 0.305: IC1.26 33.02,34.92 34.29,36.2 38.1,36.2 38.73,35.56 38.73,34.13 40.16,32.7 44.13,32.7 46.35,30.48 R11.2
RESET
  Top 0.254: 10.16,27.3 22.86,27.3
  Top 0.305: IC1.1 36.2,29.84 33.66,27.3 31.11,27.3 22.86,27.3 | 10.16,27.3 8.89,26.04 5.08,26.04 | 5.08,26.04 5.08,27.3 4.45,27.94 4.13,27.94 | ISP.5 5.08,26.04 | UART.1 6.67,31.75 2.54,31.75 1.91,31.11 1.91,29.84 3.81,27.94 4.13,27.94 | 4.13,27.94 PORTC.7
  Bottom 0.305: R28.1 13.49,36.2 UART.1
RXD  (via drill 0.7)
  Top 0.305: PORTD.1 54.61,48.26 52.39,46.04 51.44,46.04 50.48,45.09 45.09,45.09 43.81,43.81 43.81,42.55 41.91,40.64 40.32,40.64 39.85,40.16 39.85,38.58 39.21,37.94 39.21,36.35 38.58,35.72 38.58,34.13 IC1.2 33.02,32.38 v31.75,31.11
  Bottom 0.305: R26.2 22.86,29.84 22.86,30.48 23.5,31.11 v31.75,31.11
SCK/LED4
  Top 0.305: IC1.19 27.94,52.7 27.3,53.34 27.3,55.88 26.67,56.52 23.02,56.52 20.48,53.98 12.06,53.98 11.43,53.34 PORTB.6
  Bottom 0.305: IC1.19 27.94,52.7 27.3,53.34 27.3,55.88 26.04,57.15 20.95,57.15 20.32,57.78 19.05,57.78 R20.2 | ISP.3 6.99,22.23 6.99,23.18 6.35,23.81 6.35,51.44 5.71,52.07 5.71,53.34 PORTB.6
SW1
  Top 0.305: PORTB.1 5.08,66.04 6.99,64.14 6.99,63.5 8.26,62.23 25.4,62.23 27.3,64.14 30.48,64.14 31.75,62.87 IC1.14 38.26,64.29 43.02,64.29 R22.1
SW2
  Top 0.305: IC1.4 38.58,39.21 38.58,40.8 39.21,41.43 39.21,41.91 41.27,41.91 42.55,43.18 42.55,45.09 43.18,45.72 43.18,47.94 43.81,48.58 47.62,48.58 48.26,49.21 53.34,49.21 53.82,49.69 53.82,51.28 55.88,53.34 PORTD.3
  Bottom 0.305: R21.2 52.7,53.34 PORTD.3
TXD
  Top 0.305: R27.2 30.32,31.11 32.23,33.02 34.92,33.02 IC1.3 38.58,36.67 38.58,38.26 39.21,38.89 39.21,40.48 39.85,41.12 39.85,41.27 41.59,41.27 43.18,42.86 43.18,44.45 44.45,45.72 45.72,45.72 48.58,48.58 53.66,48.58 55.88,50.8 PORTD.2
V+
  Top 0.61: C3.2 53.34,12.7 IC2.IN
  Top 0.813: D2.C D1.C 40.64,15.88 37.47,12.7 VIN.1
  Bottom 0.61: D6.C D5.C | 5.71,7.62 7.62,7.62 | 7.62,7.62 15.24,7.62 | VBATT.1 7.62,4.45 7.62,7.62
  Bottom 0.813: VIN.1 33.66,8.26 27.94,8.26 | 27.94,8.26 27.94,13.97 | 27.94,13.97 H-BRIDGE.4 | 27.94,8.26 15.88,8.26 15.24,7.62 | 5.71,7.62 4.45,8.89 D6.C | 46.99,15.88 C7.+ | IC2.IN 53.34,14.61 52.07,15.88 46.99,15.88 | C6.2 31.11,10.79 27.94,13.97 | D1.C 46.99,15.88
VCC  (via drill 0.7)
  Top 0.406: H-BRIDGE.9 v21.59,11.43
  Top 0.508: 31.11,38.73 32.38,40.01 32.38,41.27 36.2,45.09 IC1.7 39.37,45.09 C1.2 40.01,46.99 40.96,47.94 40.96,50.96 41.91,51.91 41.91,52.7 40.01,54.61 v40.01,55.24 | v19.05,23.5 17.78,24.77 v15.88,24.77 | ISP.2 4.45,15.88 5.71,15.88 6.99,17.14 6.99,20.32 10.16,23.5 UART.6
  Top 0.61: C4.2 47.62,12.7 IC2.OUT | R14.1 17.14,73.66 18.41,72.39 R23.1 | R28.2 23.97,37.94 24.77,38.73 25.4,38.73 | 31.11,38.73 25.4,38.73 | 25.4,38.73 C11.+
  Top 0.813: 5V.1 LED5.A | R13.1 44.45,73.66 REF2.2 46.99,68.5 R7.1 44.45,66.04 41.91,68.58 41.27,68.58 | REF3.2 53.34,39.37 54.61,40.64 R29.S R30.S | REF4.2 53.34,28.57 54.61,29.84 R30.S | R30.S 57.78,25.4 58.42,24.77 58.42,20.32 C8.+ 51.44,17.78 48.26,14.61 IC2.OUT | R3.2 H-BRIDGE.9 | 41.91,31.11 AD4.3 | 41.91,31.11 AD5.3 | R14.1 12.7,73.66 REF1.2 10.16,68.5 7.62,65.96 R5.1 10,63.5 v14.61,63.5 24.77,63.5 26.67,65.41 31.75,65.41 32.38,64.77 36.83,64.77 40.64,68.58 41.27,68.58 | 41.27,68.58 R24.1 | v43.18,23.5 41.91,23.5 | 41.91,23.5 R1.2 | 41.91,23.5 41.91,31.11
  Bottom 0.406: C5.2 19.68,9.53 v21.59,11.43
  Bottom 0.508: C1.2 42.55,41.91 44.45,41.91 46.99,39.37 REF3.2 | v40.01,55.24 41.75,56.99 41.75,65.25 42.47,65.96 R7.1 | 21.59,48.26 15.4,54.45 15.4,56.83 13.49,58.74 13.49,62.39 v14.61,63.5 | v19.05,23.5 R3.2 | v15.88,24.77 12.38,24.77 UART.6 8.57,26.04 8.57,33.66 | 8.57,33.66 8.57,36.2 12.38,40.01 15.24,40.01 18.26,43.02 B1.2 | 8.57,33.66 UART.2 | 21.59,48.26 19.21,48.26 B1.2 | L1.1 24.13,49.53 22.86,49.53 21.59,48.26 | B1.2
  Bottom 0.61: I2C.3 22.86,35.56 23.5,36.2 24.77,36.2 25.4,36.83 C11.+ | SERVO2.2 SERVO1.2 46.35,39.37 REF3.2
  Bottom 0.813: 5V.1 56.52,11.43 55.88,12.06 C8.+ 53.34,20.32 46.35,20.32 v43.18,23.5

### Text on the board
Top: crf.nu
Bottom: v 1.0 | Introbot | 09 | crf.nu | + | - | Victor Stensson
tNames: 1 | 4 | 4 | 1 | + | + | + | + | PB0 | Introbot09 | crf.nu | PD0 | PC0 | 4 | S | SDA | SCL | VCC | GND | RESET | + | 1 | - | VCC | 4 | RXD | + | GND | - | TXD | S | S | 1 | VCC | 1 | - | + | + | - | + | -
